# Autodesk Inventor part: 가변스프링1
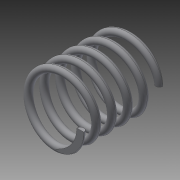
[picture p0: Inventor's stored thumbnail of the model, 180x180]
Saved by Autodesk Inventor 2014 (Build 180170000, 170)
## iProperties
Created: 2016-02
Part Number: 가변스프링1
Material: 일반
Document SubType Name: Modeling
Designer: Owner
Density: 1 g/cm^3
Appearance: 기본값
Mass: 0.823605 g
Surface Area: 16.7342 cm^2
Volume: 0.823605 cm^3
Author: Owner
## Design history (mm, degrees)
sketch "스케치1"
  geometry: L1 (0, 0)-(8.5, 0); L2 (8.5, 0)-(8.5, 22.511); L3 (8.5, 22.511)-(0, 22.511); L4 (0, 22.511)-(0, 0); C1 r 1 at (8.5, 0)
  constraints: 8 end point, 2 parallel, 1 centre point, 1 coincident, 1 horizontal, 1 perpendicular
  dimensions: "d0" = 2 diameter of C1; "d1" = 17 diameter of L2 L4; "d2" = 22.51063 distance of L1.end L2.end (derived)
feature "코일1" sketch "스케치1" pitch "d3" = 10; turns "d5" = 5; dims "d4" = 22.51063 (= d2), "d6" = 0, angle "d7" = 90 deg, angle "d8" = 90 deg, "d9" = 0, "d10" = 0
sketch "스케치2"
  geometry: L1 (-9.5, 0)-(-7.5, 0) reference; 1 further point
  constraints: 1 horizontal alignment
extrude "돌출1" cut sketch "스케치2" distance "d11" = 10; taper "d12" = 0 deg
node "작업 평면1"
sketch "스케치3"
  geometry: L1 (1, 0)-(-1, 0) reference; 1 further point
  constraints: 1 horizontal alignment
extrude "돌출2" cut sketch "스케치3" distance "d13" = 10; taper "d14" = 0 deg
node "솔리드1"
node "절단 모서리 투영1"
node "절단 모서리 투영2"
